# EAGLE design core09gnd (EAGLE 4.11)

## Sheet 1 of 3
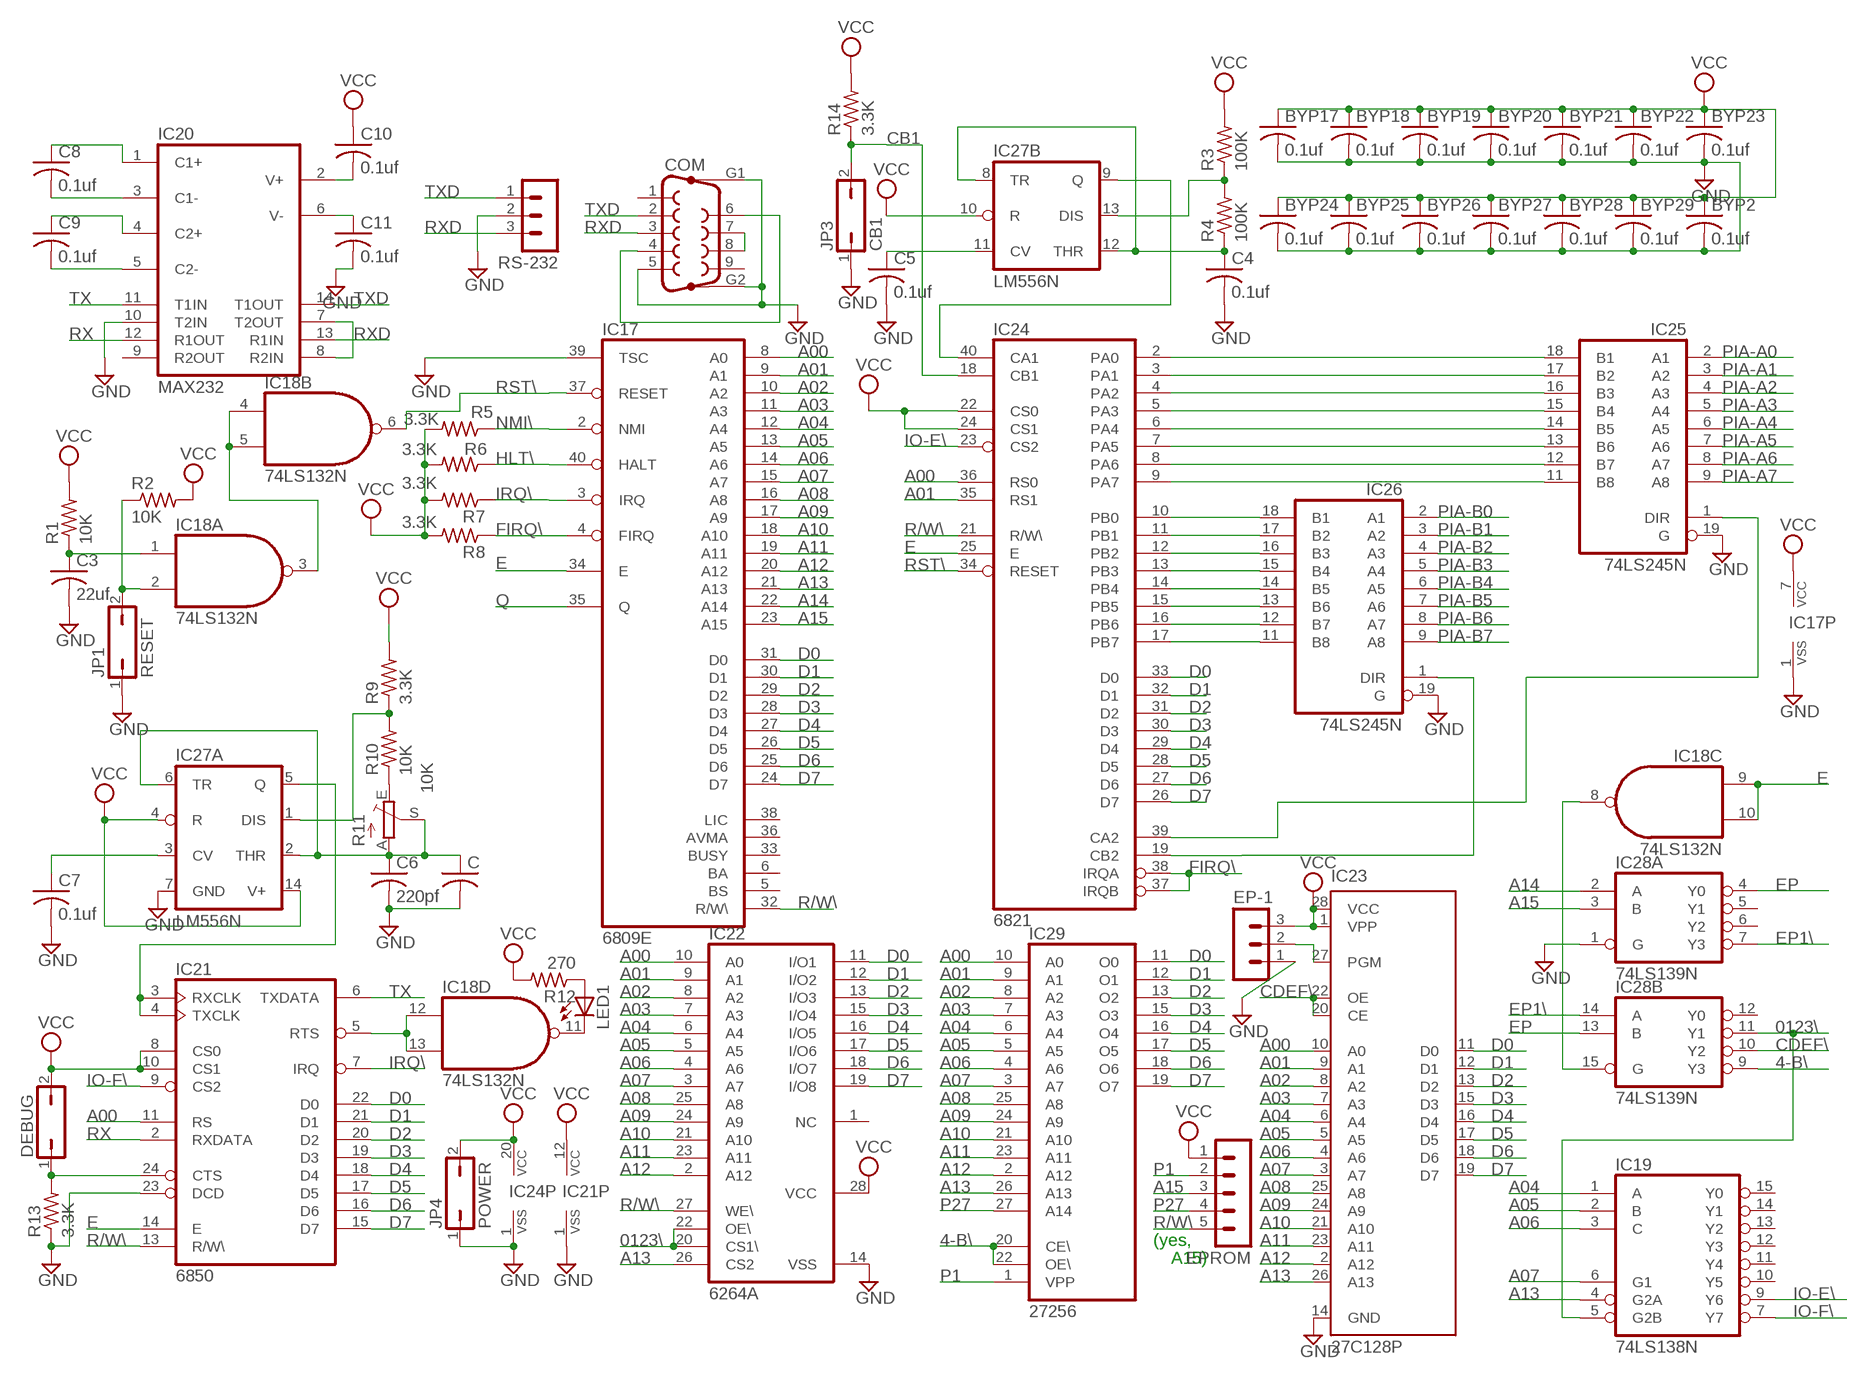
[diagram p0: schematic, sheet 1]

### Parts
BYP2  0.1uf  C-US050-025X075  [C050-025X075]
BYP17  0.1uf  C-US050-025X075  [C050-025X075]
BYP18  0.1uf  C-US050-025X075  [C050-025X075]
BYP19  0.1uf  C-US050-025X075  [C050-025X075]
BYP20  0.1uf  C-US050-025X075  [C050-025X075]
BYP21  0.1uf  C-US050-025X075  [C050-025X075]
BYP22  0.1uf  C-US050-025X075  [C050-025X075]
BYP23  0.1uf  C-US050-025X075  [C050-025X075]
BYP24  0.1uf  C-US050-025X075  [C050-025X075]
BYP25  0.1uf  C-US050-025X075  [C050-025X075]
BYP26  0.1uf  C-US050-025X075  [C050-025X075]
BYP27  0.1uf  C-US050-025X075  [C050-025X075]
BYP28  0.1uf  C-US050-025X075  [C050-025X075]
BYP29  0.1uf  C-US050-025X075  [C050-025X075]
C  C-US050-025X075  [C050-025X075]
C3  22uf  C-US102-054X133  [C102-054X133]
C4  0.1uf  C-US050-025X075  [C050-025X075]
C5  0.1uf  C-US050-025X075  [C050-025X075]
C6  220pf  C-US050-025X075  [C050-025X075]
C7  0.1uf  C-US050-025X075  [C050-025X075]
C8  0.1uf  C-US050-025X075  [C050-025X075]
C9  0.1uf  C-US050-025X075  [C050-025X075]
C10  0.1uf  C-US050-025X075  [C050-025X075]
C11  0.1uf  C-US050-025X075  [C050-025X075]
COM  F09HP  [F09HP]
DEBUG  JP1Q  [JP1]
EP-1  MA03-1  [MA03-1]
EPROM  MA05-1  [MA05-1]
IC17  6809E  [DIL40]
IC18  74LS132N  74LS00N  [DIL14]
IC19  74LS138N  [DIL16]
IC20  MAX232  [DIL16]
IC21  6850  [DIL24]
IC22  6264A  [DIL28-6]
IC23  27C128P  [DIL28-6]
IC24  6821  [DIL40]
IC25  74LS245N  [DIL20]
IC26  74LS245N  [DIL20]
IC27  LM556N  [DIL14]
IC28  74LS139N  [DIL16]
IC29  27256  [DIL28]
JP1  RESET  JP1Q  [JP1]
JP3  CB1  JP1Q  [JP1]
JP4  POWER  JP1Q  [JP1]
LED1  LED3MM  [LED3MM]
R1  10K  R-US_0207/7  [0207/7]
R2  10K  R-US_0207/7  [0207/7]
R3  100K  R-US_0207/7  [0207/7]
R4  100K  R-US_0207/7  [0207/7]
R5  3.3K  R-US_0207/7  [0207/7]
R6  3.3K  R-US_0207/7  [0207/7]
R7  3.3K  R-US_0207/7  [0207/7]
R8  3.3K  R-US_0207/7  [0207/7]
R9  3.3K  R-US_0207/7  [0207/7]
R10  10K  R-US_0207/7  [0207/7]
R11  10K  TRIM_EU-B90P  [SP19L]
R12  270  R-US_0207/7  [0207/7]
R13  3.3K  R-US_0207/7  [0207/7]
R14  3.3K  R-US_0207/7  [0207/7]
RS-232  MA03-1  [MA03-1]

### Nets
4-B\: IC28.9(B:Y3) IC29.20(CE\) IC29.22(OE\)
0123\: IC19.5(G2B) IC22.20(CS1\) IC22.22(OE\) IC28.11(B:Y1)
A00: IC17.8(A0) IC21.11(RS) IC22.10(A0) IC23.10(A0) IC24.36(RS0) IC29.10(A0)
A01: IC17.9(A1) IC22.9(A1) IC23.9(A1) IC24.35(RS1) IC29.9(A1)
A02: IC17.10(A2) IC22.8(A2) IC23.8(A2) IC29.8(A2)
A03: IC17.11(A3) IC22.7(A3) IC23.7(A3) IC29.7(A3)
A04: IC17.12(A4) IC19.1(A) IC22.6(A4) IC23.6(A4) IC29.6(A4)
A05: IC17.13(A5) IC19.2(B) IC22.5(A5) IC23.5(A5) IC29.5(A5)
A06: IC17.14(A6) IC19.3(C) IC22.4(A6) IC23.4(A6) IC29.4(A6)
A07: IC17.15(A7) IC19.6(G1) IC22.3(A7) IC23.3(A7) IC29.3(A7)
A08: IC17.16(A8) IC22.25(A8) IC23.25(A8) IC29.25(A8)
A09: IC17.17(A9) IC22.24(A9) IC23.24(A9) IC29.24(A9)
A10: IC17.18(A10) IC22.21(A10) IC23.21(A10) IC29.21(A10)
A11: IC17.19(A11) IC22.23(A11) IC23.23(A11) IC29.23(A11)
A12: IC17.20(A12) IC22.2(A12) IC23.2(A12) IC29.2(A12)
A13: IC17.21(A13) IC19.4(G2A) IC22.26(CS2) IC23.26(A13) IC29.26(A13)
A14: IC17.22(A14) IC28.2(A:A)
A15: EPROM.3 IC17.23(A15) IC28.3(A:B)
CB1: IC24.18(CB1) JP3.2 R14.1
CDEF\: IC23.20(CE) IC23.22(OE) IC28.10(B:Y2)
D0: IC17.31(D0) IC21.22(D0) IC22.11(I/O1) IC23.11(D0) IC24.33(D0) IC29.11(O0)
D1: IC17.30(D1) IC21.21(D1) IC22.12(I/O2) IC23.12(D1) IC24.32(D1) IC29.12(O1)
D2: IC17.29(D2) IC21.20(D2) IC22.13(I/O3) IC23.13(D2) IC24.31(D2) IC29.13(O2)
D3: IC17.28(D3) IC21.19(D3) IC22.15(I/O4) IC23.15(D3) IC24.30(D3) IC29.15(O3)
D4: IC17.27(D4) IC21.18(D4) IC22.16(I/O5) IC23.16(D4) IC24.29(D4) IC29.16(O4)
D5: IC17.26(D5) IC21.17(D5) IC22.17(I/O6) IC23.17(D5) IC24.28(D5) IC29.17(O5)
D6: IC17.25(D6) IC21.16(D6) IC22.18(I/O7) IC23.18(D6) IC24.27(D6) IC29.18(O6)
D7: IC17.24(D7) IC21.15(D7) IC22.19(I/O8) IC23.19(D7) IC24.26(D7) IC29.19(O7)
E: IC17.34(E) IC18.9(C:I0) IC18.10(C:I1) IC21.14(E) IC24.25(E) ; also sheet 3
EP: IC28.4(A:Y0) IC28.13(B:B)
EP1\: IC28.7(A:Y3) IC28.14(B:A)
FIRQ\: IC17.4(FIRQ) IC24.37(IRQB) IC24.38(IRQA) R8.1
GND: BYP2.2 BYP17.2 BYP18.2 BYP19.2 BYP20.2 BYP21.2 BYP22.2 BYP23.2 BYP24.2 BYP25.2 BYP26.2 BYP27.2 BYP28.2 BYP29.2 C3.2 C4.2 C5.2 C6.2 C7.2 C11.2 C.2 COM.5 COM.G1 COM.G2 EP-1.1 IC17.1(VSS) IC17.39(TSC) IC20.10(T2IN) IC21.1(VSS) IC21.23(DCD) IC22.14(VSS) IC23.14(GND) IC24.1(VSS) IC25.19(G) IC26.19(G) IC27.7(A:GND) IC28.1(A:G) JP1.1 JP3.1 JP4.1 R13.1 RS-232.2 ; also sheet 2,3
HLT\: IC17.40(HALT) R5.1
IO-E\: IC19.9(Y6) IC24.23(CS2)
IO-F\: IC19.7(Y7) IC21.9(CS2)
IRQ\: IC17.3(IRQ) IC21.7(IRQ) R7.1
N$1: COM.4 COM.6
N$4: EP-1.2 IC23.27(PGM)
N$5: IC24.2(PA0) IC25.18(B1)
N$6: IC18.3(A:O) IC18.4(B:I0) IC18.5(B:I1)
N$21: C3.1 IC18.1(A:I0) R1.1
N$22: IC18.2(A:I1) JP1.2 R2.1
N$23: IC21.3(RXCLK) IC21.4(TXCLK) IC27.5(A:Q)
N$24: IC24.10(PB0) IC26.18(B1)
N$25: IC24.11(PB1) IC26.17(B2)
N$27: C6.1 C.1 IC27.2(A:THR) IC27.6(A:TR) R11.A R11.S
N$28: IC27.1(A:DIS) R9.1 R10.2
N$94: IC24.12(PB2) IC26.16(B3)
N$124: IC24.13(PB3) IC26.15(B4)
N$125: IC24.14(PB4) IC26.14(B5)
N$126: IC24.15(PB5) IC26.13(B6)
N$127: IC24.16(PB6) IC26.12(B7)
N$128: IC24.17(PB7) IC26.11(B8)
N$129: IC24.3(PA1) IC25.17(B2)
N$130: IC24.4(PA2) IC25.16(B3)
N$131: IC24.5(PA3) IC25.15(B4)
N$132: IC24.6(PA4) IC25.14(B5)
N$133: IC24.7(PA5) IC25.13(B6)
N$134: IC24.8(PA6) IC25.12(B7)
N$135: IC24.9(PA7) IC25.11(B8)
N$136: IC24.19(CB2) IC26.1(DIR)
N$137: IC24.39(CA2) IC25.1(DIR)
N$138: IC24.40(CA1) IC27.9(B:Q)
N$140: C4.1 IC27.8(B:TR) IC27.12(B:THR) R4.1
N$141: IC27.13(B:DIS) R3.1 R4.2
N$142: C5.1 IC27.11(B:CV)
N$143: R10.1 R11.E
N$145: COM.7 COM.8
N$147: IC18.12(D:I0) IC18.13(D:I1) IC21.5(RTS)
N$148: IC18.11(D:O) LED1.K(C)
N$149: LED1.A R12.1
N$150: DEBUG.1 IC21.24(CTS) R13.2
N$151: IC18.8(C:O) IC28.15(B:G)
N$153: IC20.7(T2OUT) IC20.8(R2IN)
N$154: C7.1 IC27.3(A:CV)
N$155: C9.2 IC20.5(C2-)
N$156: C9.1 IC20.4(C2+)
N$157: C8.2 IC20.3(C1-)
N$158: C8.1 IC20.1(C1+)
N$159: C11.1 IC20.6(V-)
N$160: C10.2 IC20.2(V+)
NMI\: IC17.2(NMI) R6.1
P1: EPROM.2 IC29.1(VPP)
P27: EPROM.4 IC29.27(A14)
PIA-A0: IC25.2(A1) ; also sheet 2
PIA-A1: IC25.3(A2) ; also sheet 2
PIA-A2: IC25.4(A3) ; also sheet 2
PIA-A3: IC25.5(A4) ; also sheet 2
PIA-A4: IC25.6(A5) ; also sheet 2
PIA-A5: IC25.7(A6) ; also sheet 2
PIA-A6: IC25.8(A7) ; also sheet 2
PIA-A7: IC25.9(A8) ; also sheet 2
PIA-B0: IC26.2(A1) ; also sheet 2
PIA-B1: IC26.3(A2) ; also sheet 2
PIA-B2: IC26.4(A3) ; also sheet 2
PIA-B3: IC26.5(A4) ; also sheet 2
PIA-B4: IC26.6(A5) ; also sheet 2
PIA-B5: IC26.7(A6) ; also sheet 2
PIA-B6: IC26.8(A7) ; also sheet 2
PIA-B7: IC26.9(A8) ; also sheet 2
Q: IC17.35(Q) ; also sheet 3
R/W\: EPROM.5 IC17.32(R/W\) IC21.13(R/W\) IC22.27(WE\) IC24.21(R/W\)
RST\: IC17.37(RESET) IC18.6(B:O) IC24.34(RESET)
RX: IC20.12(R1OUT) IC21.2(RXDATA)
RXD: COM.3 IC20.13(R1IN) RS-232.3
TX: IC20.11(T1IN) IC21.6(TXDATA)
TXD: COM.2 IC20.14(T1OUT) RS-232.1
VCC [Power]: BYP2.1 BYP17.1 BYP18.1 BYP19.1 BYP20.1 BYP21.1 BYP22.1 BYP23.1 BYP24.1 BYP25.1 BYP26.1 BYP27.1 BYP28.1 BYP29.1 C10.1 DEBUG.2 EP-1.3 EPROM.1 IC17.7(VCC) IC21.8(CS0) IC21.10(CS1) IC21.12(VCC) IC22.28(VCC) IC23.1(VPP) IC23.28(VCC) IC24.20(VCC) IC24.22(CS0) IC24.24(CS1) IC27.4(A:R) IC27.10(B:R) IC27.14(A:V+) JP4.2 R1.2 R2.2 R3.2 R5.2 R6.2 R7.2 R8.2 R9.2 R12.2 R14.2 ; also sheet 2,3
Unconnected: COM.1 COM.9 IC17.5(BS) IC17.6(BA) IC17.33(BUSY) IC17.36(AVMA) IC17.38(LIC) IC19.10(Y5) IC19.11(Y4) IC19.12(Y3) IC19.13(Y2) IC19.14(Y1) IC19.15(Y0) IC20.9(R2OUT) IC22.1(NC) IC28.5(A:Y1) IC28.6(A:Y2) IC28.12(B:Y0)

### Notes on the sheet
- (yes,
- A15)

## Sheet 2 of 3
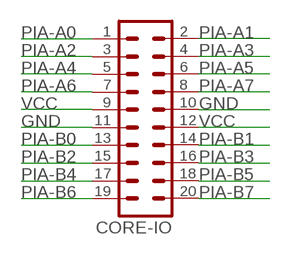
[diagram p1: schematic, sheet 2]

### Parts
CORE-IO  MA10-2  [MA10-2]

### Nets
GND: CORE-IO.10 CORE-IO.11 ; also sheet 1,3
PIA-A0: CORE-IO.1 ; also sheet 1
PIA-A1: CORE-IO.2 ; also sheet 1
PIA-A2: CORE-IO.3 ; also sheet 1
PIA-A3: CORE-IO.4 ; also sheet 1
PIA-A4: CORE-IO.5 ; also sheet 1
PIA-A5: CORE-IO.6 ; also sheet 1
PIA-A6: CORE-IO.7 ; also sheet 1
PIA-A7: CORE-IO.8 ; also sheet 1
PIA-B0: CORE-IO.13 ; also sheet 1
PIA-B1: CORE-IO.14 ; also sheet 1
PIA-B2: CORE-IO.15 ; also sheet 1
PIA-B3: CORE-IO.16 ; also sheet 1
PIA-B4: CORE-IO.17 ; also sheet 1
PIA-B5: CORE-IO.18 ; also sheet 1
PIA-B6: CORE-IO.19 ; also sheet 1
PIA-B7: CORE-IO.20 ; also sheet 1
VCC [Power]: CORE-IO.9 CORE-IO.12 ; also sheet 1,3

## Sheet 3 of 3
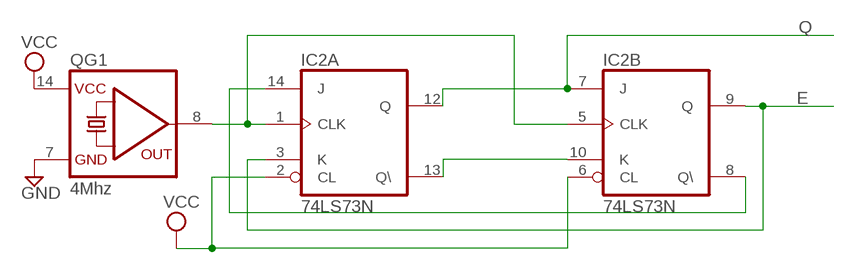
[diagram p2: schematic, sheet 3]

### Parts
IC2  74LS73N  [DIL14]
QG1  4Mhz  QG5860  [DIL14S]

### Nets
E: IC2.3(A:K) IC2.9(B:Q) ; also sheet 1
GND: QG1.7(GND) ; also sheet 1,2
N$2: IC2.1(A:CLK) IC2.5(B:CLK) QG1.8(OUT)
N$3: IC2.10(B:K) IC2.13(A:Q\)
N$7: IC2.8(B:Q\) IC2.14(A:J)
Q: IC2.7(B:J) IC2.12(A:Q) ; also sheet 1
VCC [Power]: IC2.2(A:CL) IC2.6(B:CL) QG1.14(VCC) ; also sheet 1,2

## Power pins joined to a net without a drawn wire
GND: IC2.11(P:GND) IC18.7(P:GND) IC19.8(GND) IC20.15(GND) IC25.10(GND) IC26.10(GND) IC28.8(P:GND) IC29.14(GND)
VCC: IC2.4(P:VCC) IC18.14(P:VCC) IC19.16(VCC) IC20.16(VCC) IC25.20(VCC) IC26.20(VCC) IC28.16(P:VCC) IC29.28(VCC)

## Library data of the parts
BYP2 BYP17-BYP29 C C3-C11 = rcl:C-US: CAPACITOR, American symbol
COM = con-subd:F09HP: SUB-D
CORE-IO = con-lstb:MA10-2: PIN HEADER
DEBUG JP1 JP3 JP4 = jumper:JP1Q: JUMPER
EP-1 RS-232 = con-lstb:MA03-1: PIN HEADER
EPROM = con-lstb:MA05-1: PIN HEADER
IC2 = 74xx-us:74*73: Dual J-K FLIP FLOP, clear
IC17 = micro-motorola:6809E: MICROCONTROLLER/MEMORY DEVICE
IC18 = 74xx-us:74*00: Quad 2-input NAND gate
IC19 = 74xx-us:74*138: 3-line to 8-line DECODER/DEMULTIPLEXER
IC20 = maxim:MAX232: RS232 TRANSEIVER
IC21 = micro-motorola:6850: MICROCONTROLLER/MEMORY DEVICE
IC22 = memory-hitachi:6264A: MEMORY
IC23 = microchip:27*128: CMOS EPROM 128 K (16 K x 8)
IC24 = micro-motorola:6821: MICROCONTROLLER/MEMORY DEVICE
IC25 IC26 = 74xx-us:74*245: Octal BUS TRANSCEIVER, 3-state
IC27 = linear:*556: Dual TIMER
IC28 = 74xx-us:74*139: Dual 2-line to 4-line DECODER/DEMULTIPLEXER
IC29 = memory:27256: MEMORY
LED1 = led:LED: LED
QG1 = crystal:QG5860: CRYSTAL RESONATOR
R1-R10 R12-R14 = rcl:R-US_: RESISTOR, American symbol
R11 = pot:TRIM_EU-: POTENTIOMETER

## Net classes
1 Power: width 0.508 mm, drill 0.254 mm, clearance 0.254 mm

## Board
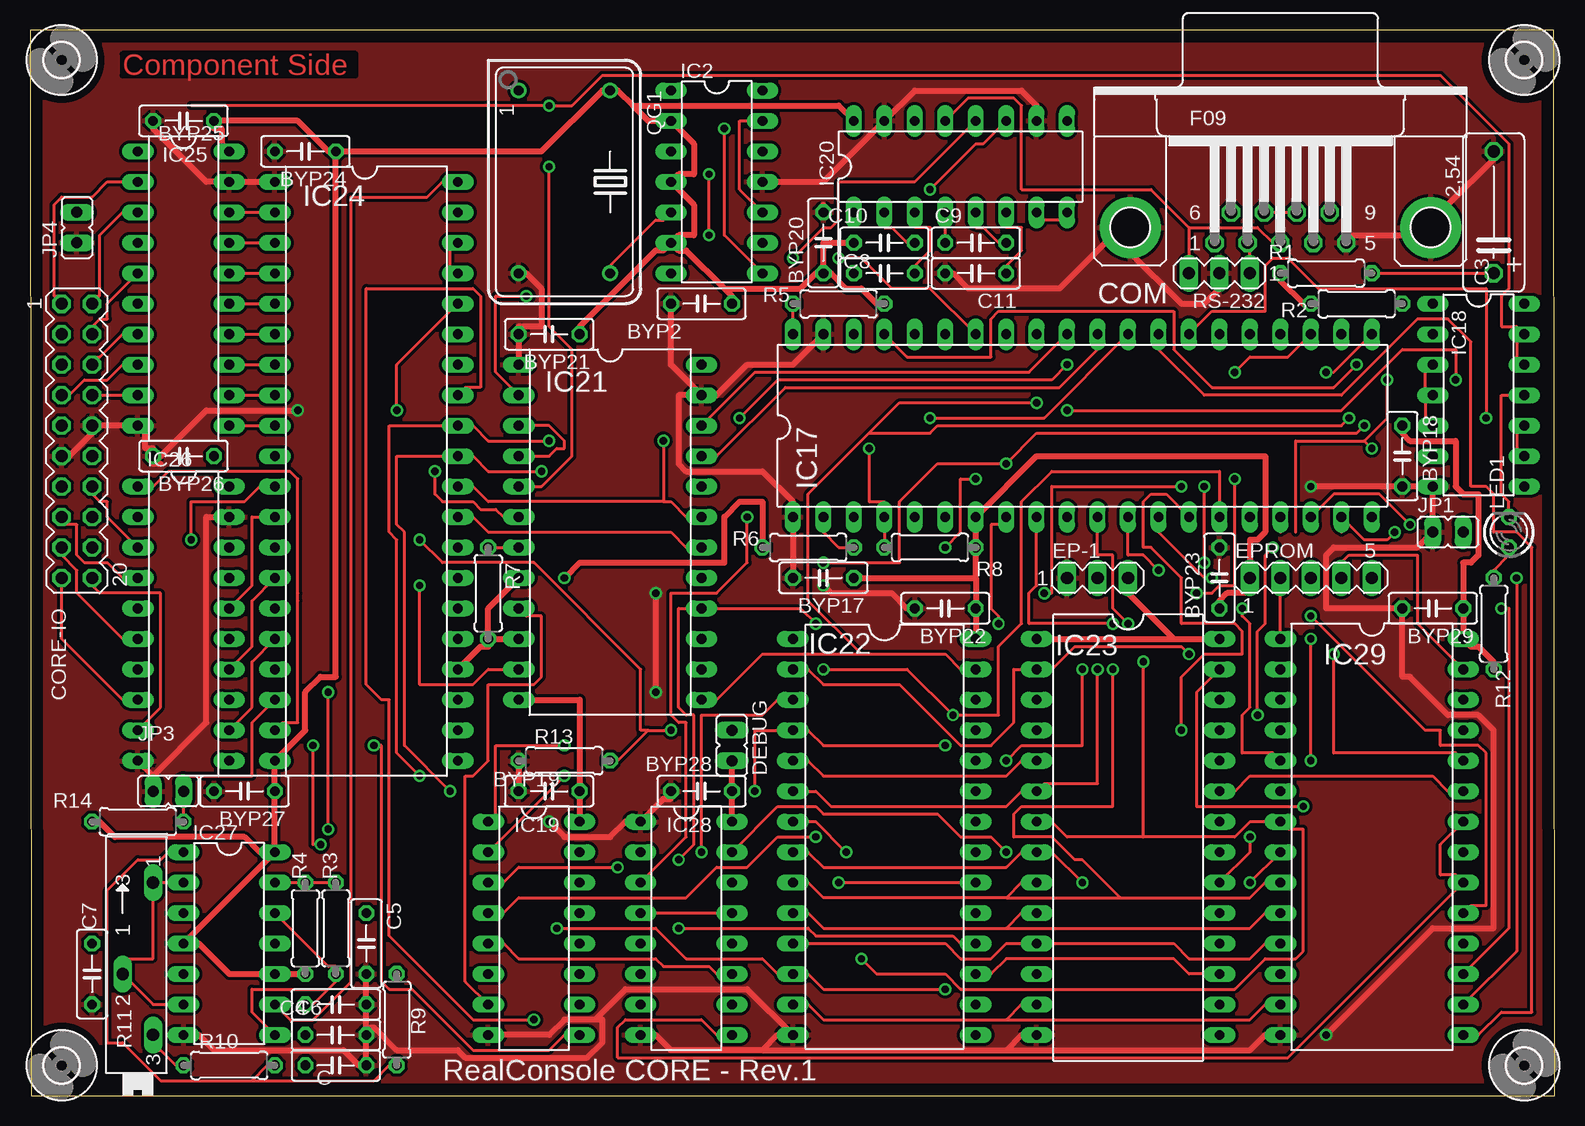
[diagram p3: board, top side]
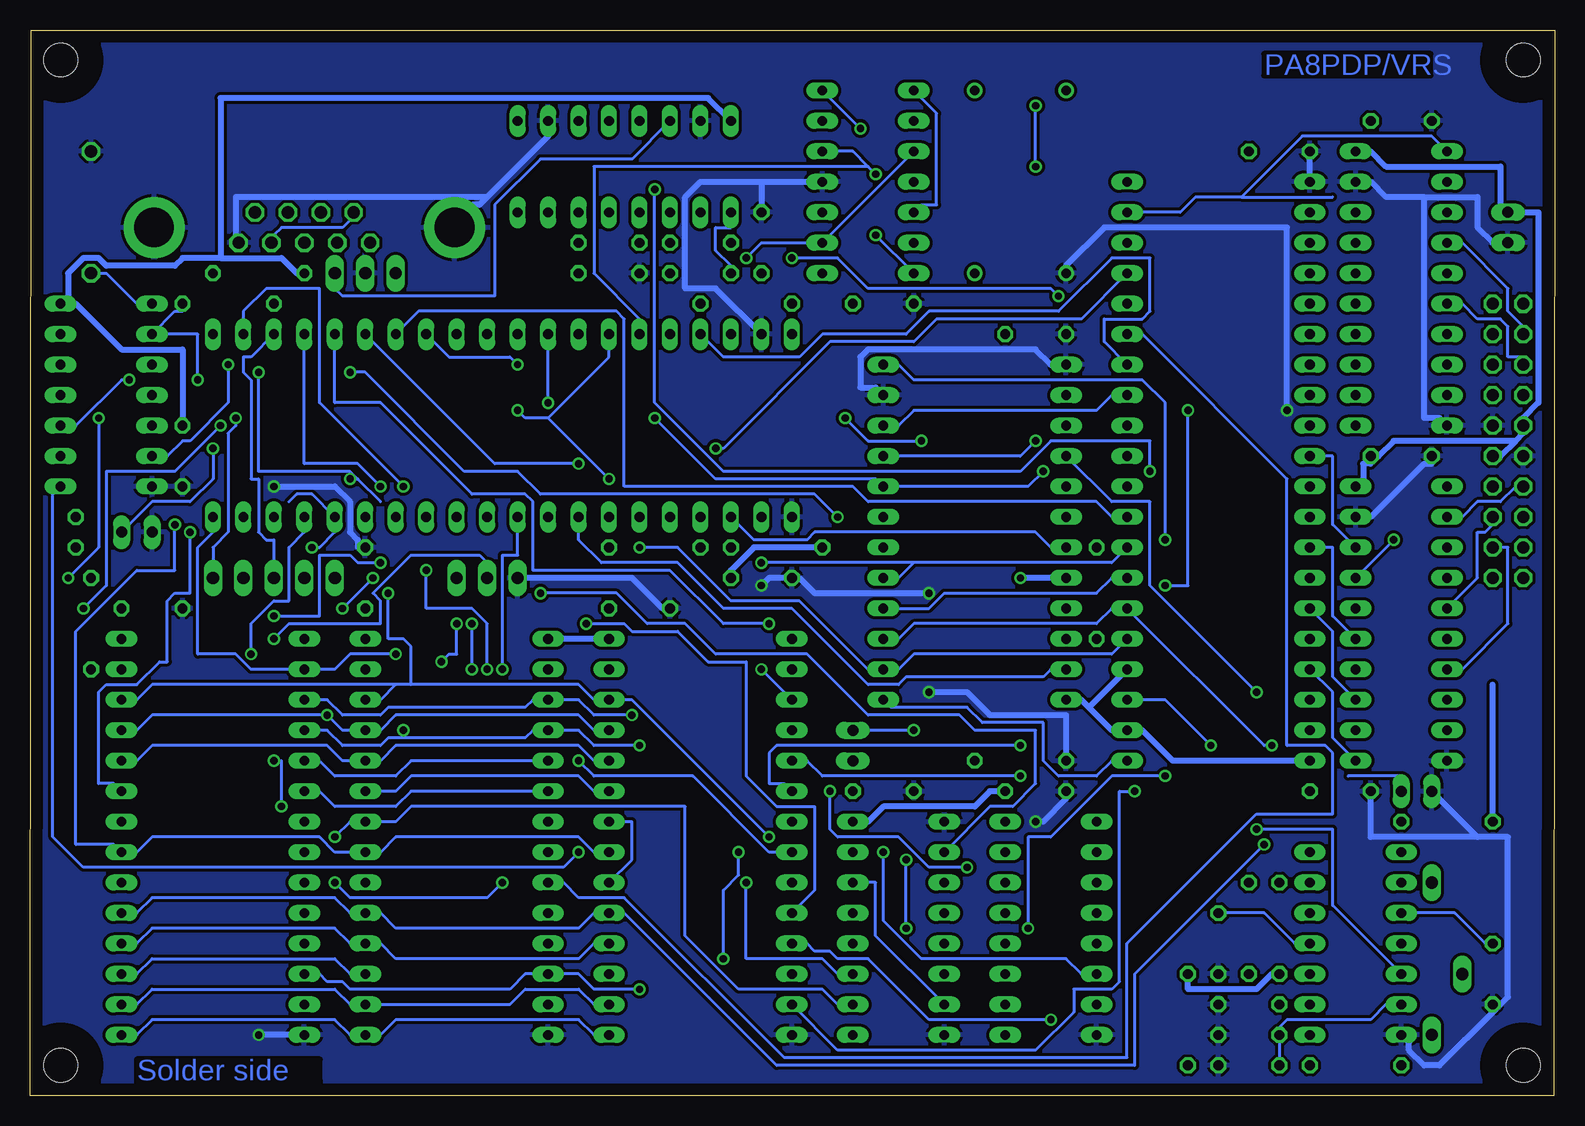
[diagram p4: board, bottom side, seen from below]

Size 127.11 x 88.87 mm. Coordinates in mm from the lower left corner, seen from the top.
Outline: 0.1,0 127.11,0 127.01,88.87 0,88.87 0.1,0
Copper layers (1*16): Top 0.035mm / dielectric 1.5mm / Bottom 0.035mm
Design rules "olimex10mil": minimum track width 10mil, minimum drill 24mil, track to track 10mil, track to pad 10mil, pad to pad 10mil, via to via 10mil, smd to smd 10mil, copper to edge 40mil, drill to drill 10mil, minimum pad ring 10mil, minimum via ring 8mil, stop-mask expansion 0mil, vias tented up to drill 0mil, thermal gap 10mil

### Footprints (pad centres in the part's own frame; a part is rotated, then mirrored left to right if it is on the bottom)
C050-025X075 = drill 0.813 octagon: 1 -2.54,0; 2 2.54,0
C102-054X133 = drill 1.016 octagon: 1 -5.08,0; 2 5.08,0
F09HP = drill 1.016 octagon: 1 -5.486,-1.27; 2 -2.743,-1.27; 3 0,-1.27; 4 2.743,-1.27; 5 5.486,-1.27; 6 -4.115,1.27; 7 -1.372,1.27; 8 1.372,1.27; 9 4.115,1.27 | drill 3.302 pad 5.08 round: G1 -12.522,0; G2 12.522,0
MA10-2 = drill 1.016 octagon: 1 -11.43,-1.27; 2 -11.43,1.27; 3 -8.89,-1.27; 4 -8.89,1.27; 5 -6.35,-1.27; 6 -6.35,1.27; 7 -3.81,-1.27; 8 -3.81,1.27; 9 -1.27,-1.27; 10 -1.27,1.27; 11 1.27,-1.27; 12 1.27,1.27; 13 3.81,-1.27; 14 3.81,1.27; 15 6.35,-1.27; 16 6.35,1.27; 17 8.89,-1.27; 18 8.89,1.27; 19 11.43,-1.27; 20 11.43,1.27
JP1 = drill 0.914 long: 1 0,-1.27; 2 0,1.27
MA03-1 = drill 1.016 long: 1 -2.54,0; 2 0,0; 3 2.54,0
MA05-1 = drill 1.016 long: 1 -5.08,0; 2 -2.54,0; 3 0,0; 4 2.54,0; 5 5.08,0
DIL14 = drill 0.813 long: 1 -7.62,-3.81; 2 -5.08,-3.81; 3 -2.54,-3.81; 4 0,-3.81; 5 2.54,-3.81; 6 5.08,-3.81; 7 7.62,-3.81; 8 7.62,3.81; 9 5.08,3.81; 10 2.54,3.81; 11 0,3.81; 12 -2.54,3.81; 13 -5.08,3.81; 14 -7.62,3.81
DIL40 = drill 0.813 long: 1 -24.13,-7.62; 2 -21.59,-7.62; 3 -19.05,-7.62; 4 -16.51,-7.62; 5 -13.97,-7.62; 6 -11.43,-7.62; 7 -8.89,-7.62; 8 -6.35,-7.62; 9 -3.81,-7.62; 10 -1.27,-7.62; 11 1.27,-7.62; 12 3.81,-7.62; 13 6.35,-7.62; 14 8.89,-7.62; 15 11.43,-7.62; 16 13.97,-7.62; 17 16.51,-7.62; 18 19.05,-7.62; 19 21.59,-7.62; 20 24.13,-7.62; 21 24.13,7.62; 22 21.59,7.62; 23 19.05,7.62; 24 16.51,7.62; 25 13.97,7.62; 26 11.43,7.62; 27 8.89,7.62; 28 6.35,7.62; 29 3.81,7.62; 30 1.27,7.62; 31 -1.27,7.62; 32 -3.81,7.62; 33 -6.35,7.62; 34 -8.89,7.62; 35 -11.43,7.62; 36 -13.97,7.62; 37 -16.51,7.62; 38 -19.05,7.62; 39 -21.59,7.62; 40 -24.13,7.62
DIL16 = drill 0.813 long: 1 -8.89,-3.81; 2 -6.35,-3.81; 3 -3.81,-3.81; 4 -1.27,-3.81; 5 1.27,-3.81; 6 3.81,-3.81; 7 6.35,-3.81; 8 8.89,-3.81; 9 8.89,3.81; 10 6.35,3.81; 11 3.81,3.81; 12 1.27,3.81; 13 -1.27,3.81; 14 -3.81,3.81; 15 -6.35,3.81; 16 -8.89,3.81
DIL24 = drill 0.813 long: 1 -13.97,-7.62; 2 -11.43,-7.62; 3 -8.89,-7.62; 4 -6.35,-7.62; 5 -3.81,-7.62; 6 -1.27,-7.62; 7 1.27,-7.62; 8 3.81,-7.62; 9 6.35,-7.62; 10 8.89,-7.62; 11 11.43,-7.62; 12 13.97,-7.62; 13 13.97,7.62; 14 11.43,7.62; 15 8.89,7.62; 16 6.35,7.62; 17 3.81,7.62; 18 1.27,7.62; 19 -1.27,7.62; 20 -3.81,7.62; 21 -6.35,7.62; 22 -8.89,7.62; 23 -11.43,7.62; 24 -13.97,7.62
DIL28-6 = drill 0.813 long: 1 -16.51,-7.62; 2 -13.97,-7.62; 3 -11.43,-7.62; 4 -8.89,-7.62; 5 -6.35,-7.62; 6 -3.81,-7.62; 7 -1.27,-7.62; 8 1.27,-7.62; 9 3.81,-7.62; 10 6.35,-7.62; 11 8.89,-7.62; 12 11.43,-7.62; 13 13.97,-7.62; 14 16.51,-7.62; 15 16.51,7.62; 16 13.97,7.62; 17 11.43,7.62; 18 8.89,7.62; 19 6.35,7.62; 20 3.81,7.62; 21 1.27,7.62; 22 -1.27,7.62; 23 -3.81,7.62; 24 -6.35,7.62; 25 -8.89,7.62; 26 -11.43,7.62; 27 -13.97,7.62; 28 -16.51,7.62
DIL20 = drill 0.813 long: 1 -11.43,-3.81; 2 -8.89,-3.81; 3 -6.35,-3.81; 4 -3.81,-3.81; 5 -1.27,-3.81; 6 1.27,-3.81; 7 3.81,-3.81; 8 6.35,-3.81; 9 8.89,-3.81; 10 11.43,-3.81; 11 11.43,3.81; 12 8.89,3.81; 13 6.35,3.81; 14 3.81,3.81; 15 1.27,3.81; 16 -1.27,3.81; 17 -3.81,3.81; 18 -6.35,3.81; 19 -8.89,3.81; 20 -11.43,3.81
DIL28 = drill 0.813 long: 1 -16.51,-7.62; 2 -13.97,-7.62; 3 -11.43,-7.62; 4 -8.89,-7.62; 5 -6.35,-7.62; 6 -3.81,-7.62; 7 -1.27,-7.62; 8 1.27,-7.62; 9 3.81,-7.62; 10 6.35,-7.62; 11 8.89,-7.62; 12 11.43,-7.62; 13 13.97,-7.62; 14 16.51,-7.62; 15 16.51,7.62; 16 13.97,7.62; 17 11.43,7.62; 18 8.89,7.62; 19 6.35,7.62; 20 3.81,7.62; 21 1.27,7.62; 22 -1.27,7.62; 23 -3.81,7.62; 24 -6.35,7.62; 25 -8.89,7.62; 26 -11.43,7.62; 27 -13.97,7.62; 28 -16.51,7.62
LED3MM = drill 0.813 octagon: A -1.27,0; K 1.27,0
DIL14S = drill 0.813 round: 1 -7.62,-3.81; 7 7.62,-3.81; 8 7.62,3.81; 14 -7.62,3.81
0207/7 = drill 0.813 octagon: 1 -3.81,0; 2 3.81,0
SP19L = drill 1.016 long: A 5.715,-1.27; E -6.985,-1.27; S -1.905,1.27
2,8 = hole 2.8: 0,0

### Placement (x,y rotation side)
BYP2  55.98,66.05 180 top
BYP17  66.14,43.19 180 top
BYP18  114.4,53.35 270 top
BYP19  43.28,25.41 180 top
BYP20  66.14,71.13 90 top
BYP21  43.28,63.51 180 top
BYP22  76.3,40.65 180 top
BYP23  99.16,43.19 90 top
BYP24  22.96,78.75 180 top
BYP25  12.8,81.29 180 top
BYP26  12.8,53.35 180 top
BYP27  17.88,25.41 180 top
BYP28  55.98,25.41 180 top
BYP29  116.94,40.65 180 top
C  25.5,2.55 0 top
C3  122.02,73.67 90 top
C4  25.5,7.63 0 top
C5  28.04,12.71 270 top
C6  25.5,5.09 0 top
C7  5.18,10.17 270 top
C8  71.22,68.59 0 top
C9  78.84,71.13 0 top
C10  71.22,71.13 0 top
C11  78.84,68.59 180 top
COM  104.24,72.4 0 top
CORE-IO  3.91,54.62 270 top
DEBUG  58.52,29.22 180 top
EP-1  89,43.19 0 top
EPROM  106.78,43.19 0 top
IC2  57.25,76.21 270 top
IC17  87.73,55.89 0 top
IC18  120.75,58.43 270 top
IC19  42.01,13.98 270 top
IC20  77.57,77.48 0 top
IC21  48.36,47 270 top
IC22  71.22,21.6 270 top
IC23  91.54,21.6 270 top
IC24  28.04,52.08 270 top
IC25  12.8,67.32 270 top
IC26  12.8,39.38 270 top
IC27  16.61,12.71 270 top
IC28  54.71,13.98 270 top
IC29  111.86,21.6 270 top
JP1  118.21,47 270 top
JP3  11.53,25.41 270 top
JP4  3.91,72.4 0 top
LED1  123.29,47 90 top
QG1  44.55,76.21 270 top
R1  108.05,68.59 180 top
R2  110.59,66.05 180 top
R3  22.96,13.98 270 top
R4  25.5,13.98 90 top
R5  67.41,66.05 0 top
R6  64.87,45.73 180 top
R7  38.2,41.92 270 top
R8  75.03,45.73 0 top
R9  30.58,6.36 90 top
R10  16.61,2.55 0 top
R11  8.99,12.08 90 top
R12  122.02,39.38 270 top
R13  44.55,27.95 0 top
R14  8.99,22.87 180 top
RS-232  99.16,68.59 180 top
U$3  [2,8]  2.64,86.37 0 top
U$4  [2,8]  2.64,2.55 0 top
U$5  [2,8]  124.56,86.37 0 top
U$6  [2,8]  124.56,2.55 0 top

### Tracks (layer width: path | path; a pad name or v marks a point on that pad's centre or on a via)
4-B\
  Top 0.254: IC28.9 57.25,5.09 55.98,6.36 49.63,6.36 48.99,5.73 48.99,3.19 104.87,3.19 IC29.20 118.84,18.43 117.57,18.43 117.57,20.97 IC29.22
0123\  (via drill 0.61)
  Top 0.254: IC28.11 57.25,10.17 56.61,10.81 52.8,10.81 52.17,11.44 40.74,11.44 39.47,12.71 IC19.5 | v67.41,17.79 IC22.20
  Bottom 0.254: IC22.20 76.93,19.7 76.93,22.87 IC22.22 | v67.41,17.79 67.41,11.44 61.06,11.44 59.79,10.17 IC28.11
A00  (via drill 0.61)
  Top 0.254: 81.38,13.98 66.14,13.98 64.87,15.25 IC22.10 | 81.38,13.98 82.65,15.25 IC23.10 | 81.38,13.98 101.7,13.98 102.97,15.25 IC29.10 | v30.58,57.16 30.58,60.97 IC24.36 | v32.48,42.56 32.48,34.3 36.93,34.3 38.2,35.57 IC21.11 | v80.74,39.38 80.74,40.02 80.11,40.65 80.11,47.64 80.74,47.64 IC17.8
  Bottom 0.254: IC21.11 42.01,35.57 42.64,34.94 54.07,34.94 54.71,34.3 57.25,34.3 63.6,40.65 69.31,40.65 73.12,44.46 79.47,44.46 81.38,46.37 IC17.8 | v30.58,57.16 30.58,42.56 v32.48,42.56 | v80.74,39.38 77.57,39.38 76.93,38.75 73.12,38.75 70.58,36.21 67.41,36.21 67.41,26.68 64.87,24.14 61.69,24.14 61.69,17.16 IC22.10
A01  (via drill 0.61)
  Top 0.254: 81.38,16.52 66.14,16.52 64.87,17.79 IC22.9 | 81.38,16.52 82.65,17.79 IC23.9 | 81.38,16.52 90.9,16.52 | 90.9,16.52 101.7,16.52 102.97,17.79 IC29.9 | v90.27,35.57 90.27,24.14 82.65,24.14 82.01,23.51 82.01,21.6 85.19,21.6 87.09,19.7 87.73,19.7 90.9,16.52 | v90.27,39.38 83.28,39.38 83.28,41.92 83.92,42.56 IC17.9
  Bottom 0.254: v90.27,35.57 v90.27,39.38 | IC24.35 34.39,63.51 22.32,51.45 22.32,29.22 19.15,29.22 18.51,28.59 18.51,23.51 24.86,23.51 35.66,12.71 35.66,3.19 64.23,3.19 77.57,16.52 81.38,16.52 82.65,17.79 IC23.9
A02  (via drill 0.61)
  Top 0.254: IC22.8 64.87,20.33 66.14,19.06 81.38,19.06 82.65,20.33 IC23.8 85.19,20.33 v87.73,17.79 | v101.7,17.79 IC29.8 | v87.73,35.57 87.73,29.22 82.65,29.22 v81.38,27.95
  Bottom 0.254: v101.7,17.79 100.43,16.52 89,16.52 v87.73,17.79 | v87.73,35.57 87.73,45.1 86.46,45.1 IC17.10 | v81.38,27.95 80.11,26.68 71.85,26.68 65.5,20.33 IC22.8
A03  (via drill 0.61)
  Top 0.254: v68.04,20.33 65.5,22.87 IC22.7 | v69.31,11.44 70.58,10.17 76.3,10.17 77.57,8.9 100.43,8.9 102.97,11.44 105.51,11.44 106.14,12.08 106.14,22.24 104.87,22.24 IC29.7 101.7,22.87 100.43,21.6 92.81,21.6 | 92.81,21.6 86.46,21.6 85.19,22.87 IC23.7 | v91.54,39.38 90.27,40.65 90.27,45.1 89,45.1 IC17.11 | 92.81,21.6 v92.81,36.21
  Bottom 0.254: v68.04,20.33 68.04,18.43 69.31,17.16 v69.31,11.44 | v91.54,39.38 91.54,36.84 92.17,36.84 v92.81,36.21
A04  (via drill 0.61)
  Top 0.254: v44.55,29.22 38.83,29.22 38.83,23.51 IC19.1 | IC22.6 65.5,25.41 66.77,24.14 81.38,24.14 82.65,25.41 IC23.6 84.55,26.05 89,26.05 v89,35.57 | v94.08,43.83 92.81,45.1 91.54,45.1 IC17.12
  Bottom 0.254: v44.55,29.22 64.87,29.22 65.5,28.59 65.5,26.05 64.23,26.05 IC22.6 | IC29.6 102.97,25.41 101.7,24.14 96.62,24.14 95.35,25.41 IC23.6 | v94.08,43.83 94.08,40.65 90.27,40.65 89,39.38 v89,35.57
A05  (via drill 0.61)
  Top 0.254: IC19.2 v44.55,26.68 | IC23.5 82.65,27.95 81.38,26.68 66.14,26.68 64.87,27.95 IC22.5 | v98.52,43.19 97.89,43.19 94.08,47 IC17.13 | v101.06,40.65 101.06,40.02 101.7,39.38 101.7,32.4 101.06,31.76 101.06,28.59 103.6,28.59 IC29.5
  Bottom 0.254: v44.55,26.68 61.06,26.68 62.33,27.95 IC22.5 | IC29.5 102.97,27.95 101.7,26.68 96.62,26.68 95.35,27.95 IC23.5 | v101.06,40.65 v98.52,43.19
A06  (via drill 0.61)
  Top 0.254: v48.99,19.06 40.74,19.06 39.47,17.79 IC19.3 | v60.42,25.41 60.42,30.49 IC22.4 64.87,30.49 66.14,29.22 v76.3,29.22 | v95.98,30.49 95.98,34.94 97.89,36.84 101.06,36.84 101.06,38.75 100.43,39.38 95.98,39.38 95.98,43.19 93.44,45.73 92.81,45.73 92.81,49.54 93.44,50.18 94.71,50.18 IC17.14
  Bottom 0.254: v48.99,19.06 52.17,19.06 54.71,21.6 59.79,21.6 60.42,22.24 v60.42,25.41 | 95.98,29.86 85.82,29.86 85.19,30.49 IC23.4 81.38,30.49 80.11,29.22 v76.3,29.22 | 95.98,29.86 97.25,29.86 97.89,29.22 101.06,29.22 102.33,30.49 IC29.4 | 95.98,29.86 v95.98,30.49
A07  (via drill 0.61)
  Top 0.254: v55.98,20.33 55.98,31.76 61.06,31.76 62.33,33.03 IC22.3 | IC17.15 99.16,52.08 85.19,52.08 82.65,49.54 82.65,39.38 80.74,37.48 80.74,31.76 v76.93,31.76 73.12,35.57 v66.14,35.57
  Bottom 0.254: IC29.3 102.33,33.03 101.06,31.76 97.89,31.76 97.25,32.4 85.82,32.4 85.19,33.03 IC23.3 81.38,33.03 80.11,31.76 v76.93,31.76 | v55.98,20.33 55.98,14.62 52.8,11.44 40.74,11.44 39.47,10.17 IC19.6 | IC22.3 v66.14,35.57
A08  (via drill 0.61)
  Top 0.254: v103.6,45.73 102.97,45.1 102.97,39.38 102.33,38.75 v102.33,31.76
  Bottom 0.254: IC22.25 80.11,30.49 81.38,31.76 96.62,31.76 97.89,30.49 IC23.25 101.06,30.49 v102.33,31.76 116.94,31.76 118.21,30.49 IC29.25 | 105.51,49.54 104.87,50.18 103.6,50.18 IC17.16 101.7,47 102.97,45.73 v103.6,45.73
A09  (via drill 0.61)
  Top 0.254: v108.68,36.84 108.68,28.59 118.84,28.59 IC29.24 | IC17.17 104.24,47
  Bottom 0.254: IC22.24 80.11,27.95 81.38,29.22 96.62,29.22 97.89,27.95 IC23.24 101.06,27.95 102.33,29.22 116.94,29.22 118.21,27.95 IC29.24 | v108.68,36.84 108.68,39.38 106.78,41.29 105.51,41.29 105.51,45.73 104.24,47 IC17.17
A10  (via drill 0.61)
  Top 0.254: v115.03,47.64 112.49,50.18 108.68,50.18 IC17.18
  Bottom 0.254: IC22.21 80.11,20.33 81.38,21.6 96.62,21.6 97.89,20.33 IC23.21 101.7,20.33 102.97,21.6 116.94,21.6 118.21,20.33 IC29.21 120.11,20.97 123.29,20.97 123.29,38.75 118.21,43.83 115.03,43.83 v115.03,47.64
A11  (via drill 0.61)
  Top 0.254: IC29.23 118.21,25.41 116.94,26.68 101.7,26.68 100.43,25.41 IC23.23 | 109.32,47 IC17.19 111.22,46.37 113.13,46.37 v113.76,47
  Bottom 0.254: IC22.23 80.11,25.41 81.38,26.68 95.35,26.68 96.62,25.41 IC23.23 | IC29.23 120.11,26.05 121.38,26.05 121.38,33.67 120.75,34.3 118.21,34.3 116.3,36.21 115.67,36.21 115.67,41.29 115.03,41.92 113.76,41.92 v113.76,47
A12  (via drill 0.61)
  Top 0.254: IC22.2 64.87,35.57 66.14,34.3 72.49,34.3 77.57,29.22 80.11,29.22 82.01,31.13 82.01,35.57 IC23.2 85.19,35.57 87.09,37.48 95.98,37.48 v96.62,36.84
  Bottom 0.254: v96.62,36.84 100.43,36.84 101.7,35.57 IC29.2 108.68,35.57 109.95,36.84 113.13,36.84 113.13,45.73 111.86,47 IC17.20
A13  (via drill 0.61)
  Top 0.254: v65.5,21.6 62.33,21.6 59.79,19.06 57.25,19.06 54.71,16.52 40.74,16.52 39.47,15.25 IC19.4 | v108.05,60.34 108.68,60.34 IC17.21 | v100.43,51.45 100.43,42.56 99.16,42.56 98.52,41.92 v97.25,41.92
  Bottom 0.254: v65.5,21.6 76.93,33.03 IC22.26 80.11,33.03 81.38,34.3 95.35,34.3 | 96.62,34.3 97.89,33.03 IC23.26 | 95.35,34.3 96.62,34.3 | 96.62,34.3 116.94,34.3 118.21,33.03 IC29.26 | v108.05,60.34 108.05,52.08 100.43,52.08 99.79,51.45 | 95.35,34.3 95.35,37.48 95.98,38.11 97.25,38.11 v97.25,41.92 | 99.79,51.45 97.89,49.54 | v100.43,51.45 99.79,51.45
A14  (via drill 0.61)
  Top 0.254: v95.98,50.81 85.19,50.81 85.19,41.92 v84.55,41.92
  Bottom 0.254: v95.98,50.81 102.97,57.8 102.97,67.32 107.41,67.32 109.32,65.42 IC17.22 | IC28.2 47.09,24.14 45.18,24.14 43.28,26.05 43.28,30.49 48.36,30.49 49.63,31.76 57.25,31.76 62.33,36.84 69.95,36.84 72.49,39.38 75.66,39.38 78.2,41.92 v84.55,41.92
A15  (via drill 0.61)
  Top 0.254: v59.79,48.27 59.79,44.46 57.25,41.92 53.44,41.92 53.44,31.76 54.07,31.13 54.71,31.13 54.71,21.6 IC28.3 | v100.43,60.34 101.7,61.61 104.87,61.61 IC17.23
  Bottom 0.254: v59.79,48.27 61.69,50.18 84.55,50.18 86.46,52.08 90.9,52.08 99.16,60.34 v100.43,60.34 | EPROM.3 106.78,46.37 107.41,46.37 108.05,47 108.05,51.45 108.68,51.45 108.68,59.7 109.32,60.34 109.32,61.61 108.68,61.61 IC17.23
CB1
  Top 0.254: R14.1 JP3.2 12.8,26.68 18.51,26.68 18.51,31.13 IC24.18
  Bottom 0.254: 17.24,26.68 12.8,26.68 JP3.2
CDEF\  (via drill 0.61)
  Top 0.254: v101.7,21.6 101.7,20.33 IC23.20
  Bottom 0.254: IC28.10 59.79,7.63 61.06,8.9 68.04,8.9 72.49,13.35 72.49,24.14 95.35,24.14 96.62,22.87 IC23.22 100.43,22.87 v101.7,21.6
D0  (via drill 0.61)
  Top 0.254: IC22.11 76.3,12.71 77.57,11.44 80.11,11.44 81.38,12.71 IC23.11 95.35,12.71 96.62,11.44 101.7,11.44 102.97,12.71 IC29.11 | IC17.31 83.28,60.34 60.42,60.34 IC21.22 | v42.01,6.36 36.93,6.36 29.94,13.35 29.94,33.03 29.31,33.03 28.04,34.3 28.04,67.32 36.93,67.32 37.56,66.69 37.56,59.07 36.29,59.07 IC24.33
  Bottom 0.254: IC24.33 36.93,58.43 38.2,57.16 53.44,57.16 54.71,55.89 IC21.22 | v42.01,6.36 52.17,6.36 57.25,11.44 59.79,11.44 60.42,12.08 61.69,12.08 62.33,12.71 IC22.11
D1  (via drill 0.61)
  Top 0.254: v76.3,8.9 66.14,8.9 64.87,10.17 IC22.12 62.33,10.17 61.06,11.44 54.71,11.44 52.17,13.98 v43.91,13.98 | IC21.21 57.25,53.35 62.96,59.07 85.82,59.07 89,62.24 IC17.30 | v43.28,54.62 38.2,54.62 36.93,55.89 IC24.32 29.94,55.89 29.94,47 30.58,46.37 30.58,28.59 v32.48,26.68
  Bottom 0.254: v76.3,8.9 80.11,8.9 81.38,10.17 IC23.12 85.82,10.17 87.09,8.9 100.43,8.9 101.06,9.54 102.33,9.54 102.97,10.17 IC29.12 | v43.28,54.62 44.55,53.35 IC21.21 | v43.91,13.98 43.91,21.6 42.01,21.6 36.93,26.68 v32.48,26.68
D2  (via drill 0.61)
  Top 0.254: 81.38,6.36 66.14,6.36 64.87,7.63 IC22.13 | 81.38,6.36 82.65,7.63 IC23.13 | 81.38,6.36 101.7,6.36 102.97,7.63 IC29.13 | v42.64,52.08 38.2,52.08 36.93,53.35 IC24.31 30.58,53.35 30.58,47.64 31.21,47 31.21,29.22 v35.02,25.41 | v75.03,56.53 84.55,56.53 IC17.29
  Bottom 0.254: v42.64,52.08 43.91,50.81 IC21.20 56.61,51.45 69.95,51.45 v75.03,56.53 | v35.02,25.41 36.29,25.41 36.29,9.54 36.93,8.9 40.1,8.9 40.1,7 43.28,3.82 59.79,3.82 IC22.13
D3  (via drill 0.61)
  Top 0.254: 52.8,49.54 38.2,49.54 36.93,50.81 IC24.30 | 52.8,49.54 53.44,49.54 54.71,48.27 IC21.19 | IC17.28 94.08,62.24 97.89,58.43 109.32,58.43 115.67,64.78 118.21,64.78 120.11,62.88 120.11,50.81 121.38,50.81 122.02,50.18 122.02,47 123.92,47 125.19,45.73 125.19,7 122.65,7 120.75,5.09 IC29.15 | v52.8,54.62 52.8,49.54 | v59.15,56.53 62.33,59.7 85.19,59.7 v86.46,60.97
  Bottom 0.254: IC22.15 80.11,5.09 81.38,6.36 96.62,6.36 97.89,5.09 IC23.15 100.43,5.09 101.7,6.36 116.94,6.36 118.21,5.09 IC29.15 | v52.8,54.62 57.25,54.62 v59.15,56.53 | v86.46,60.97 87.09,61.61 92.17,61.61 IC17.28
D4  (via drill 0.61)
  Top 0.254: IC21.18 54.71,45.73 53.44,47 38.2,47 36.93,48.27 IC24.29 | v123.92,43.19 123.92,12.08 IC29.16 | v121.38,56.53 121.38,67.32 107.41,67.32 104.87,69.86 103.6,69.86 102.97,69.23 102.97,65.42 98.52,65.42 IC17.27
  Bottom 0.254: IC22.16 80.11,7.63 81.38,8.9 85.82,8.9 87.09,7.63 IC23.16 100.43,7.63 101.7,8.9 116.94,8.9 118.21,7.63 IC29.16 | IC17.27 94.71,65.42 78.2,65.42 77.57,64.78 77.57,50.81 58.52,50.81 57.25,49.54 38.2,49.54 36.93,48.27 IC24.29 | v123.92,43.19 121.38,45.73 v121.38,56.53
D5  (via drill 0.61)
  Top 0.254: IC22.17 80.11,10.17 81.38,11.44 95.35,11.44 96.62,10.17 IC23.17 | v66.14,44.46 72.49,44.46 72.49,49.54 75.66,52.72 v81.38,52.72 83.92,55.26 110.59,55.26 v111.22,55.89 | v122.65,40.65 123.29,40.65 123.29,13.98 IC29.17
  Bottom 0.254: IC29.17 118.21,10.17 116.94,11.44 101.7,11.44 100.43,10.17 IC23.17 | 53.44,44.46 54.71,43.19 IC21.17 | 53.44,44.46 36.93,44.46 IC24.28 | v81.38,52.72 88.36,52.72 IC17.26 | 53.44,44.46 v66.14,44.46 | v122.65,40.65 120.75,42.56 120.75,52.08 115.03,52.08 v111.22,55.89
D6  (via drill 0.61)
  Top 0.254: v65.5,39.38 64.23,40.65 IC21.16 54.07,40.65 54.07,32.4 54.71,31.76 55.34,31.76 55.34,20.97 v54.07,19.7 | v54.07,13.98 64.87,13.98 65.5,13.35 76.93,13.35 77.57,12.71 IC22.18
  Bottom 0.254: IC22.18 80.11,12.71 81.38,11.44 96.62,11.44 97.89,12.71 IC23.18 100.43,12.71 101.7,13.98 116.94,13.98 118.21,12.71 IC29.18 | IC24.27 36.93,43.19 38.2,41.92 50.9,41.92 52.17,40.65 IC21.16 | v65.5,39.38 69.31,39.38 73.76,43.83 85.19,43.83 85.19,49.54 85.82,50.18 90.27,50.18 97.89,57.8 101.7,57.8 IC17.25 | v54.07,13.98 v54.07,19.7
D7  (via drill 0.61)
  Top 0.254: IC29.19 120.11,15.89 121.38,15.89 121.38,28.59 120.75,29.22 117.57,29.22 117.57,30.49 116.3,30.49 v106.78,40.02 | v23.59,29.22 23.59,20.97 v24.23,20.97 | v97.89,44.46 v97.89,50.81
  Bottom 0.254: IC21.15 54.71,38.11 53.44,39.38 38.2,39.38 36.93,40.65 IC24.26 24.23,29.22 v23.59,29.22 | IC29.19 118.21,15.25 116.94,16.52 101.7,16.52 100.43,15.25 IC23.19 97.89,15.25 96.62,13.98 81.38,13.98 80.11,15.25 IC22.19 77.57,15.25 64.87,2.55 35.02,2.55 35.02,10.17 v24.23,20.97 | v97.89,50.81 99.79,52.72 104.24,52.72 IC17.24 | v97.89,44.46 99.79,44.46 100.43,45.1 102.97,45.1 102.97,40.02 v106.78,40.02
E  (via drill 0.61)
  Top 0.254: IC18.9 123.92,53.99 123.92,55.26 IC18.10 | v67.41,69.86 69.31,69.86 71.85,67.32 75.03,67.32 IC17.34 | v118.84,59.7 118.84,62.24 114.4,62.24 109.32,57.16 v86.46,57.16 | v76.3,45.73 77.57,47 77.57,51.45 v78.84,51.45
  Bottom 0.254: IC24.25 36.93,36.84 53.44,36.84 54.71,35.57 IC21.14 57.25,35.57 62.96,41.29 68.68,41.29 73.12,45.73 v76.3,45.73 | IC2.3 IC2.9 66.14,71.13 v67.41,69.86 | v118.84,59.7 119.48,59.7 123.29,55.89 IC18.10 | v86.46,57.16 85.82,56.53 83.92,56.53 | 83.92,56.53 78.84,61.61 IC17.34 | v78.84,51.45 83.92,56.53
EP
  Top 0.254: IC28.4 IC28.13
EP1\
  Bottom 0.254: IC28.7 56.61,13.35 56.61,17.79 IC28.14
FIRQ\  (via drill 0.61)
  Top 0.254: IC24.37 35.02,69.23 35.02,70.5 IC24.38 | R8.1 IC17.4 71.22,49.54 69.95,49.54 v69.95,53.99
  Bottom 0.254: v69.95,53.99 69.31,53.99 60.42,62.88 53.44,62.88 51.53,64.78 39.47,64.78 IC24.37
GND  (via drill 0.61)
  Top 0.508: IC27.7 14.07,5.09 15.34,3.82 26.13,3.82 27.4,2.55 C.2 C6.2 28.04,5.73 | 28.04,5.73 C4.2 C5.2 | 47.09,6.36 44.55,6.36 43.28,5.09 IC19.8 | 47.09,6.36 49.63,8.9 59.79,8.9 IC22.14 62.33,5.09 61.06,3.82 | 61.06,3.82 53.44,3.82 52.17,5.09 IC28.8 | 81.38,3.82 82.65,5.09 IC23.14 | 61.06,3.82 81.38,3.82 | 81.38,3.82 101.7,3.82 102.97,5.09 IC29.14 | 47.09,6.36 47.72,6.36 47.72,4.46 46.45,3.19 36.29,3.19 35.66,3.82 30.58,3.82 28.67,5.73 28.04,5.73 | 10.89,52.72 10.26,52.72 BYP26.2 | CORE-IO.11 3.27,53.35 5.18,55.26 CORE-IO.10 IC25.10 9.62,55.26 9.62,53.99 10.26,53.99 BYP26.2 | IC21.1 BYP21.2 40.74,64.15 42.64,64.15 42.64,67.32 41.37,68.59 QG1.7 | COM.5 109.95,71.77 114.4,71.77 COM.G2 118.21,74.31 122.02,78.12 C3.2 | BYP20.2 66.14,74.31 | C11.2 76.93,68.59 78.2,67.32 85.82,67.32 89.63,71.13 COM.G1 91.54,70.5 95.98,66.05 97.89,66.05 99.16,67.32 RS-232.2 | IC20.10 83.92,82.56 82.65,83.83 73.76,83.83 IC20.15 66.14,76.21 IC2.11 | R13.1 BYP19.2 | BYP28.2 53.44,24.78 52.8,24.78 IC28.1 49.63,22.87 48.36,21.6 44.55,21.6 v43.28,22.87 | BYP17.2 IC17.1 63.6,49.54 61.06,52.08 54.71,52.08 54.07,52.72 54.07,58.43 IC21.23 | IC21.23 53.44,60.97 BYP2.2 | IC17.39 63.6,60.97 59.79,60.97 57.25,58.43 IC21.23 | v52.17,41.92 v52.17,33.67 | v66.14,42.56 66.77,41.92 71.85,41.92 73.12,40.65 BYP22.2 | v106.78,50.81 BYP18.2 IC18.7 JP1.1 115.67,45.73 108.68,45.73 108.05,45.1 108.05,40.65 BYP29.2 114.4,34.94 115.03,34.94 118.21,31.76 120.75,31.76 122.02,30.49 122.02,13.98 116.94,13.98 v108.05,5.09 | IC24.1 IC25.19 14.7,76.21 10.26,80.66 BYP25.2 | 10.26,26.68 IC26.10 | 10.26,26.68 14.7,31.13 14.7,48.27 IC26.19
  Top 0.508: JP3.1 10.26,26.68 | v22.32,57.16 14.7,57.16 10.89,53.35 BYP26.2
  Bottom 0.508: IC24.1 BYP24.2 | JP4.1 5.18,71.13 6.45,72.4 6.45,74.94 10.89,74.94 | QG1.7 40.74,69.23 37.56,72.4 22.32,72.4 v22.32,57.16 | 89,74.94 89.63,74.31 90.27,74.31 COM.G1 | 89,74.94 83.92,80.02 IC20.10 | 89,74.94 109.95,74.94 109.95,71.77 COM.5 | v43.28,22.87 42.64,22.87 40.74,24.78 BYP19.2 | v52.17,33.67 48.99,33.67 47.09,31.76 40.74,31.76 R13.1 | v52.17,41.92 61.69,41.92 62.96,43.19 BYP17.2 65.5,43.19 v66.14,42.56 | IC17.39 69.95,67.32 72.49,67.32 72.49,74.94 71.22,76.21 66.14,76.21 | IC21.1 42.01,60.97 43.28,62.24 57.25,62.24 57.88,61.61 57.88,59.07 56.61,59.07 IC21.23 | 5.18,7 3.91,8.27 3.91,21.6 6.45,21.6 | 5.18,7 9.62,2.55 10.89,2.55 12.16,3.82 12.16,4.46 IC27.7 | 6.45,21.6 JP3.1 | 5.18,7 C7.2 | 66.14,76.21 IC2.11 | 66.14,76.21 BYP20.2 | 6.45,21.6 15.34,21.6 BYP27.2 | v106.78,50.81 101.7,50.81 100.43,49.54 100.43,47 99.79,46.37 99.79,45.73 BYP23.2 | IC29.14 v108.05,5.09 | 10.89,74.94 14.07,74.94 15.34,76.21 IC25.19 | IC26.19 15.34,48.27 10.89,52.72 10.26,52.72 BYP26.2 | 10.89,74.94 10.89,56.53 9.62,56.53 IC25.10 | EP-1.1 76.93,43.19 74.39,40.65 BYP22.2
  pour Bottom: 10.26,88.73 126.59,88.66 126.69,0.75 0.58,0.83 0.48,88.73 1.37,88.76 5.41,88.73
  pour Top: 116.94,88.73 0.6,88.66 0.5,0.75 126.61,0.83 126.72,88.73 125.83,88.76 121.79,88.73
HLT\
  Top 0.254: IC17.40 R5.1
IO-E\  (via drill 0.61)
  Top 0.254: v28.67,29.22 29.31,29.22 29.31,9.54 29.94,8.9 31.85,8.9 36.93,3.82 43.28,3.82 44.55,5.09 IC19.9
  Bottom 0.254: v28.67,29.22 32.48,33.03 IC24.23
IO-F\
  Top 0.254: IC19.7 36.29,9.54 36.29,26.68 36.93,26.68 38.2,27.95 38.2,34.3 42.01,34.3 42.64,34.94 42.64,40.02 41.37,40.02 IC21.9
IRQ\
  Top 0.254: R7.1 IC21.7
  Bottom 0.254: IC17.3 66.77,46.37 62.33,46.37 61.69,47 43.28,47 42.01,45.73 IC21.7
N$1
  Bottom 0.254: COM.6 100.43,73.04 101.06,72.4 106.14,72.4 106.78,71.77 COM.4
N$2
  Top 0.254: QG1.8 48.36,69.23 52.17,73.04 52.8,73.04 IC2.5
  Bottom 0.254: IC2.1 51.53,81.93 51.53,74.31 52.8,74.31 IC2.5
N$3
  Top 0.254: IC2.10 59.15,75.58 59.15,81.29 IC2.13
N$4  (via drill 0.61)
  Top 0.254: v106.14,24.14 97.25,24.14 97.25,33.67 IC23.27 | v106.78,27.95 v106.78,38.11
  Bottom 0.254: v106.14,24.14 106.14,27.95 v106.78,27.95 | v106.78,38.11 105.51,39.38 97.89,39.38 97.89,41.29 98.52,41.92 95.35,45.1 89.63,45.1 89,44.46 EP-1.2
N$5
  Top 0.254: IC25.18 IC24.2
N$6
  Top 0.254: IC18.5 116.3,56.53 116.3,57.8 IC18.4 116.3,59.07 116.3,60.34 IC18.3
N$7  (via drill 0.61)
  Top 0.254: v57.88,80.66 57.88,71.77 IC2.8
  Bottom 0.254: v57.88,80.66 IC2.14
N$21
  Top 0.254: R1.1 C3.1
  Bottom 0.254: IC18.1 118.21,66.05 120.75,68.59 C3.1
N$22  (via drill 0.61)
  Top 0.254: 105.51,47 105.51,54.62 111.22,54.62 | 111.22,54.62 113.13,56.53 v113.13,59.7 | 111.22,54.62 v111.86,53.99
  Bottom 0.254: R2.1 114.4,65.42 115.03,65.42 IC18.2 113.13,63.51 v113.13,59.7 | v111.86,53.99 111.86,51.45 113.76,49.54 116.94,49.54 JP1.2
N$23  (via drill 0.61)
  Top 0.254: v24.86,22.24 v24.86,33.67 | IC21.3 43.28,55.89 44.55,54.62 44.55,53.99 43.91,53.99 43.28,53.35 IC21.4
  Bottom 0.254: v24.86,22.24 18.51,22.24 18.51,15.89 IC27.5 | v24.86,33.67 33.75,42.56 33.75,49.54 36.93,49.54 IC21.4
N$24
  Bottom 0.254: IC26.18 18.51,47.64 18.51,53.35 IC24.10
N$25  (via drill 0.61)
  Top 0.254: v13.43,46.37 13.43,49.54 17.88,49.54 19.15,50.81 IC24.11
  Bottom 0.254: IC26.17 v13.43,46.37
N$27
  Top 0.254: IC27.2 R11.A 10.26,11.44 7.72,11.44 R11.S 10.26,7.63 IC27.6
  Bottom 0.254: IC27.6 14.07,7.63 15.34,6.36 22.32,6.36 22.96,5.73 C6.1 C.1
N$28
  Top 0.254: 18.51,1.28 10.89,1.28 7.72,4.46 6.45,4.46 6.45,17.16 8.99,19.7 10.89,19.7 11.53,20.33 IC27.1 | 18.51,1.28 19.78,2.55 R10.2 | 18.51,1.28 28.67,1.28 29.94,2.55 R9.1
N$94
  Top 0.254: IC26.16 18.51,42.56 18.51,48.27 IC24.12
N$124
  Bottom 0.254: IC26.15 18.51,40.02 18.51,45.73 IC24.13
N$125
  Top 0.254: IC26.14 18.51,37.48 18.51,41.29 IC24.14
N$126
  Bottom 0.254: IC26.13 18.51,34.94 18.51,38.75 IC24.15
N$127
  Top 0.254: IC26.12 18.51,32.4 18.51,36.21 IC24.16
N$128
  Bottom 0.254: IC26.11 18.51,29.86 18.51,33.67 IC24.17
N$129
  Top 0.254: IC25.17 IC24.3
N$130
  Top 0.254: IC25.16 IC24.4
N$131
  Top 0.254: IC25.15 IC24.5
N$132
  Top 0.254: IC25.14 IC24.6
N$133
  Top 0.254: IC25.13 IC24.7
N$134
  Top 0.254: IC25.12 IC24.8
N$135
  Top 0.254: IC25.11 IC24.9
N$136
  Top 0.254: IC24.19 21.05,31.13 22.32,31.13 22.32,41.29 22.32,41.92 22.32,51.45 21.69,52.08 11.53,52.08 10.26,50.81 IC26.1
N$137
  Bottom 0.254: 26.13,74.94 18.51,74.94 | 26.13,74.94 29.94,74.94 31.21,73.67 IC24.39 | IC25.1 10.26,80.02 21.05,80.02 26.13,74.94
N$138
  Top 0.254: IC27.9 21.69,6.36 23.59,6.36 26.77,9.54 26.77,74.94 33.12,74.94 34.39,76.21 IC24.40
N$140
  Top 0.254: 24.86,8.9 23.59,7.63 C4.1 | 24.86,8.9 25.5,9.54 R4.1 25.5,10.81 24.86,10.81 IC27.12 | 24.86,8.9 18.51,8.9 18.51,7 IC27.8
N$141
  Top 0.254: IC27.13 R3.1 R4.2
N$142
  Bottom 0.254: IC27.11 21.69,12.71 24.23,15.25 C5.1
N$143
  Top 0.254: R10.1 12.16,2.55 10.89,3.82 10.26,3.82 R11.E
N$145
  Top 0.254: COM.7 COM.8
N$147  (via drill 0.61)
  Top 0.254: IC18.12 123.92,61.61 123.92,62.88 IC18.13 123.92,64.15 122.65,64.15 122.65,66.69 123.29,67.32 123.29,79.39 117.57,85.1 47.72,85.1 45.18,82.56 v43.28,82.56 13.43,82.56 | v43.28,77.48 43.28,64.15 45.18,62.24 45.18,53.35 42.64,50.81 IC21.5
  Bottom 0.254: v43.28,77.48 v43.28,82.56
N$148
  Top 0.254: LED1.K 123.29,49.54 122.65,50.18 122.65,58.43 IC18.11
N$149
  Top 0.254: R12.1 122.02,43.83 123.29,45.1 LED1.A
N$150  (via drill 0.61)
  Top 0.254: 51.53,30.49 48.99,27.95 R13.2 | 51.53,30.49 v53.44,30.49 | v32.48,46.37 34.39,44.46 42.01,44.46 50.9,35.57 50.9,30.49 51.53,30.49
  Bottom 0.254: v53.44,30.49 DEBUG.1 | v32.48,46.37 32.48,57.8 34.39,59.7 53.44,59.7 54.71,60.97 IC21.24
N$151  (via drill 0.61)
  Top 0.254: v81.38,20.33 80.11,21.6 77.57,21.6 75.66,23.51 66.14,23.51 65.5,24.14 62.33,24.14 IC28.15
  Bottom 0.254: v81.38,20.33 82.65,19.06 122.65,19.06 125.19,21.6 125.19,50.18 IC18.8
N$153
  Top 0.254: IC20.7 84.55,73.04 85.82,73.04 IC20.8
N$154
  Bottom 0.254: C7.1 5.81,12.71 8.35,15.25 IC27.3
N$155
  Top 0.254: C9.2 80.74,71.13 79.47,72.4 78.84,72.4 IC20.5
N$156
  Top 0.254: C9.1 IC20.4
N$157
  Top 0.254: C8.2 73.76,69.23 75.03,70.5 75.03,72.4 73.76,72.4 IC20.3
N$158
  Bottom 0.254: C8.1 68.68,69.23 69.95,70.5 69.95,72.4 68.68,72.4 IC20.1
N$159
  Top 0.254: C11.1 81.38,69.23 82.65,70.5 82.65,72.4 81.38,72.4 IC20.6
N$160
  Top 0.254: C10.2 73.12,71.13 71.85,72.4 71.22,72.4 IC20.2
NMI\
  Top 0.254: IC17.2 66.14,47 67.41,45.73 R6.1
P1
  Top 0.254: IC29.1 EPROM.2
P27
  Top 0.254: IC29.27 115.67,39.38 115.67,45.1 109.95,45.1 109.32,44.46 EPROM.4
PIA-A0
  Top 0.254: CORE-IO.1 2.64,66.69 2,66.69 2,74.31 2.64,74.94 5.18,74.94 6.45,76.21 IC25.2
PIA-A1
  Top 0.254: CORE-IO.2 5.18,66.69 5.81,66.69 5.81,71.77 7.72,73.67 IC25.3
PIA-A2
  Bottom 0.254: CORE-IO.3 2.64,64.15 3.91,65.42 3.91,67.32 7.72,71.13 IC25.4
PIA-A3
  Top 0.254: CORE-IO.4 5.18,64.15 5.81,64.78 6.45,64.78 6.45,66.05 IC25.5
PIA-A4
  Bottom 0.254: CORE-IO.5 2.64,61.61 3.91,61.61 3.91,64.15 4.54,64.78 6.45,64.78 7.72,66.05 IC25.6
PIA-A5
  Top 0.254: CORE-IO.6 5.18,61.61 5.81,61.61 7.72,63.51 IC25.7
PIA-A6
  Top 0.254: CORE-IO.7 3.27,58.43 4.54,59.7 6.45,59.7 7.72,60.97 IC25.8
PIA-A7
  Top 0.254: CORE-IO.8 IC25.9
PIA-B0
  Bottom 0.254: CORE-IO.13 3.27,50.81 4.54,49.54 6.45,49.54 7.72,48.27 IC26.2
PIA-B1
  Top 0.254: CORE-IO.14 5.18,50.18 5.81,49.54 6.45,49.54 6.45,48.27 IC26.3
PIA-B2
  Top 0.254: CORE-IO.15 2.64,47.64 3.91,47.64 3.91,45.1 4.54,44.46 6.45,44.46 7.72,43.19 IC26.4
PIA-B3
  Bottom 0.254: CORE-IO.16 5.18,47.64 5.81,47 6.45,47 6.45,43.19 IC26.5
PIA-B4
  Top 0.254: CORE-IO.17 2.64,45.1 3.91,43.83 3.91,41.92 7.72,38.11 IC26.6
PIA-B5
  Bottom 0.254: CORE-IO.18 3.91,45.73 3.91,39.38 7.72,35.57 IC26.7
PIA-B6
  Top 0.254: CORE-IO.19 2.64,38.11 7.72,33.03 IC26.8
PIA-B7
  Top 0.254: CORE-IO.20 5.18,42.56 5.81,41.92 10.89,41.92 10.89,32.4 IC26.9
Q  (via drill 0.61)
  Top 0.254: v56.61,71.77 v56.61,76.85
  Bottom 0.254: 57.25,77.48 58.52,78.75 IC2.12 | v56.61,76.85 57.25,77.48 | IC2.7 v56.61,71.77 | 57.25,77.48 80.11,77.48 80.11,68.59 76.3,64.78 IC17.35
R/W\  (via drill 0.61)
  Top 0.254: 69.31,36.84 61.06,36.84 57.25,33.03 IC21.13 | 69.31,36.84 76.3,36.84 77.57,35.57 IC22.27 | v83.92,57.8 72.49,57.8 69.95,55.26 | 69.95,55.26 64.87,50.18 64.87,41.29 69.31,36.84 | v109.95,56.53 109.32,55.89 75.66,55.89 75.03,55.26 69.95,55.26
  Bottom 0.254: IC24.21 36.93,27.95 38.2,26.68 41.37,26.68 42.64,27.95 42.64,31.13 47.72,31.13 48.99,32.4 55.34,32.4 IC21.13 | v83.92,57.8 IC17.32 | v109.95,56.53 109.95,55.89 110.59,55.26 110.59,47 111.86,45.73 EPROM.5
RST\  (via drill 0.61)
  Top 0.254: v110.59,60.97 108.68,59.07 98.52,59.07 95.35,62.24 95.35,65.42 80.74,65.42 80.11,64.78 80.11,61.61 73.12,61.61 IC17.37
  Bottom 0.254: IC24.34 37.56,62.88 37.56,64.78 34.39,64.78 33.75,65.42 33.75,69.86 36.93,69.86 41.37,65.42 52.17,65.42 54.07,63.51 61.06,63.51 62.96,61.61 69.31,61.61 IC17.37 | v110.59,60.97 110.59,57.8 113.76,54.62 114.4,54.62 115.67,53.35 IC18.6
RX  (via drill 0.61)
  Top 0.254: v41.37,66.69 38.83,66.69 38.83,60.34 IC21.2 | v63.6,69.86 66.14,72.4 66.77,72.4 67.41,73.04 67.41,76.21 73.76,76.21 IC20.12
  Bottom 0.254: v41.37,66.69 42.01,67.32 57.25,67.32 59.79,69.86 v63.6,69.86
RXD
  Top 0.254: 96.62,72.4 93.44,75.58 82.65,75.58 82.65,82.56 82.01,83.2 78.2,83.2 IC20.13 | 96.62,72.4 RS-232.3 | 96.62,72.4 102.33,72.4 103.6,71.13 COM.3
TX  (via drill 0.61)
  Top 0.254: v33.75,52.08 33.75,50.18 34.39,49.54 36.93,49.54 37.56,48.91 38.83,48.91 39.47,48.27 IC21.6 | v75.03,75.58 78.84,79.39 79.47,79.39 IC20.11
  Bottom 0.254: v33.75,52.08 33.75,54.62 42.01,54.62 44.55,52.08 69.31,52.08 75.03,57.8 v75.03,75.58
TXD
  Top 0.254: COM.2 101.7,70.5 RS-232.1
  Bottom 0.254: IC20.14 76.93,78.12 84.55,78.12 88.36,74.31 88.36,66.69 101.06,66.69 101.7,67.32 RS-232.1
VCC  (via drill 0.61)
  Top 0.508: IC24.24 37.56,37.48 38.2,37.48 R7.2 | R7.2 IC21.10 | IC21.8 38.2,40.65 R7.2 | IC28.16 BYP28.1 DEBUG.2 | IC19.16 BYP19.1 45.82,33.03 IC21.12 | R14.2 5.81,22.87 7.08,21.6 17.88,21.6 19.15,20.33 IC27.14 | IC27.14 BYP27.1 IC24.20 22.96,30.49 22.96,33.67 24.23,34.94 25.5,34.94 BYP24.1 | R3.2 IC27.10 16.61,10.17 14.07,12.71 IC27.4 IC27.14 | IC22.28 BYP22.1 78.84,43.19 | 78.84,43.19 R8.2 IC17.7 83.92,53.35 102.97,53.35 102.97,47 102.33,46.37 101.7,46.37 EPROM.1 101.7,41.92 99.79,41.92 99.16,41.29 BYP23.1 | BYP17.1 78.84,43.19 | IC23.1 95.35,38.11 | 95.35,38.11 IC23.28 | R12.2 122.02,36.21 120.75,37.48 120.11,37.48 IC29.28 BYP29.1 119.48,44.46 120.11,44.46 120.75,45.1 120.75,50.18 119.48,50.18 118.84,50.81 118.84,54.62 115.03,54.62 114.4,55.26 BYP18.1 | R2.2 106.14,66.05 104.24,67.96 R1.2 | 50.26,82.56 51.53,81.29 IC2.2 55.34,79.39 55.34,76.85 54.07,76.85 IC2.4 55.34,74.31 55.34,71.77 54.07,71.77 IC2.6 | 50.26,82.56 48.99,83.83 QG1.14 47.72,83.83 42.64,78.75 BYP24.1 | 50.26,82.56 67.41,82.56 IC20.16 | BYP20.1 66.14,71.13 C10.1 | R5.2 70.58,66.05 69.31,67.32 68.04,67.32 66.77,68.59 BYP20.1 | BYP21.1 45.82,64.15 52.17,70.5 52.8,70.5 IC2.6 | 57.88,67.32 54.71,70.5 54.07,70.5 IC2.6 | 57.88,67.32 58.52,66.69 BYP2.1 | 57.88,67.32 64.23,67.32 65.5,68.59 BYP20.1 | BYP24.1 24.86,78.75 22.32,81.29 BYP25.1 15.34,80.66 15.97,80.66 15.97,79.39 IC25.20 | 95.35,38.11 91.54,41.92 EP-1.3 | v44.55,43.19 45.82,44.46 57.88,44.46 57.88,48.27 59.15,49.54 61.06,49.54 R6.2
  Bottom 0.508: 38.83,32.4 39.47,33.03 IC21.12 | 38.83,32.4 36.93,30.49 IC24.22 34.39,30.49 31.85,27.95 IC24.20 | IC28.16 57.25,22.87 55.98,24.14 48.36,24.14 47.09,25.41 BYP19.1 | 38.83,32.4 IC24.24 | R3.2 23.59,10.17 24.86,8.9 30.58,8.9 R9.2 | R6.2 66.77,45.73 68.68,43.83 BYP17.1 | IC22.28 IC23.1 | BYP18.1 114.4,62.24 119.48,62.24 123.29,66.05 IC18.14 123.92,66.69 123.92,68.59 122.65,69.86 121.38,69.86 120.75,69.23 115.03,69.23 114.4,69.86 111.22,69.86 | 111.22,69.86 106.14,69.86 104.87,68.59 R1.2 | 3.27,54.62 2.64,55.26 CORE-IO.9 2.64,56.53 1.37,57.8 1.37,73.67 JP4.2 4.54,74.31 4.54,77.48 14.07,77.48 15.34,78.75 IC25.20 | 3.27,54.62 4.54,53.35 CORE-IO.12 | 3.27,54.62 13.43,54.62 14.7,53.35 BYP26.1 15.34,52.72 15.97,52.72 15.97,51.45 IC26.20 | 111.22,69.86 111.22,83.2 70.58,83.2 IC20.16 | R14.2 5.18,34.3 | IC21.8 v44.55,43.19

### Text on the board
Top: Component Side
Bottom: PA8PDP/VRS | Solder side
tPlace: + | RealConsole CORE - Rev.1
tValues: + | - | LO/27256 | RAM | HI/27128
